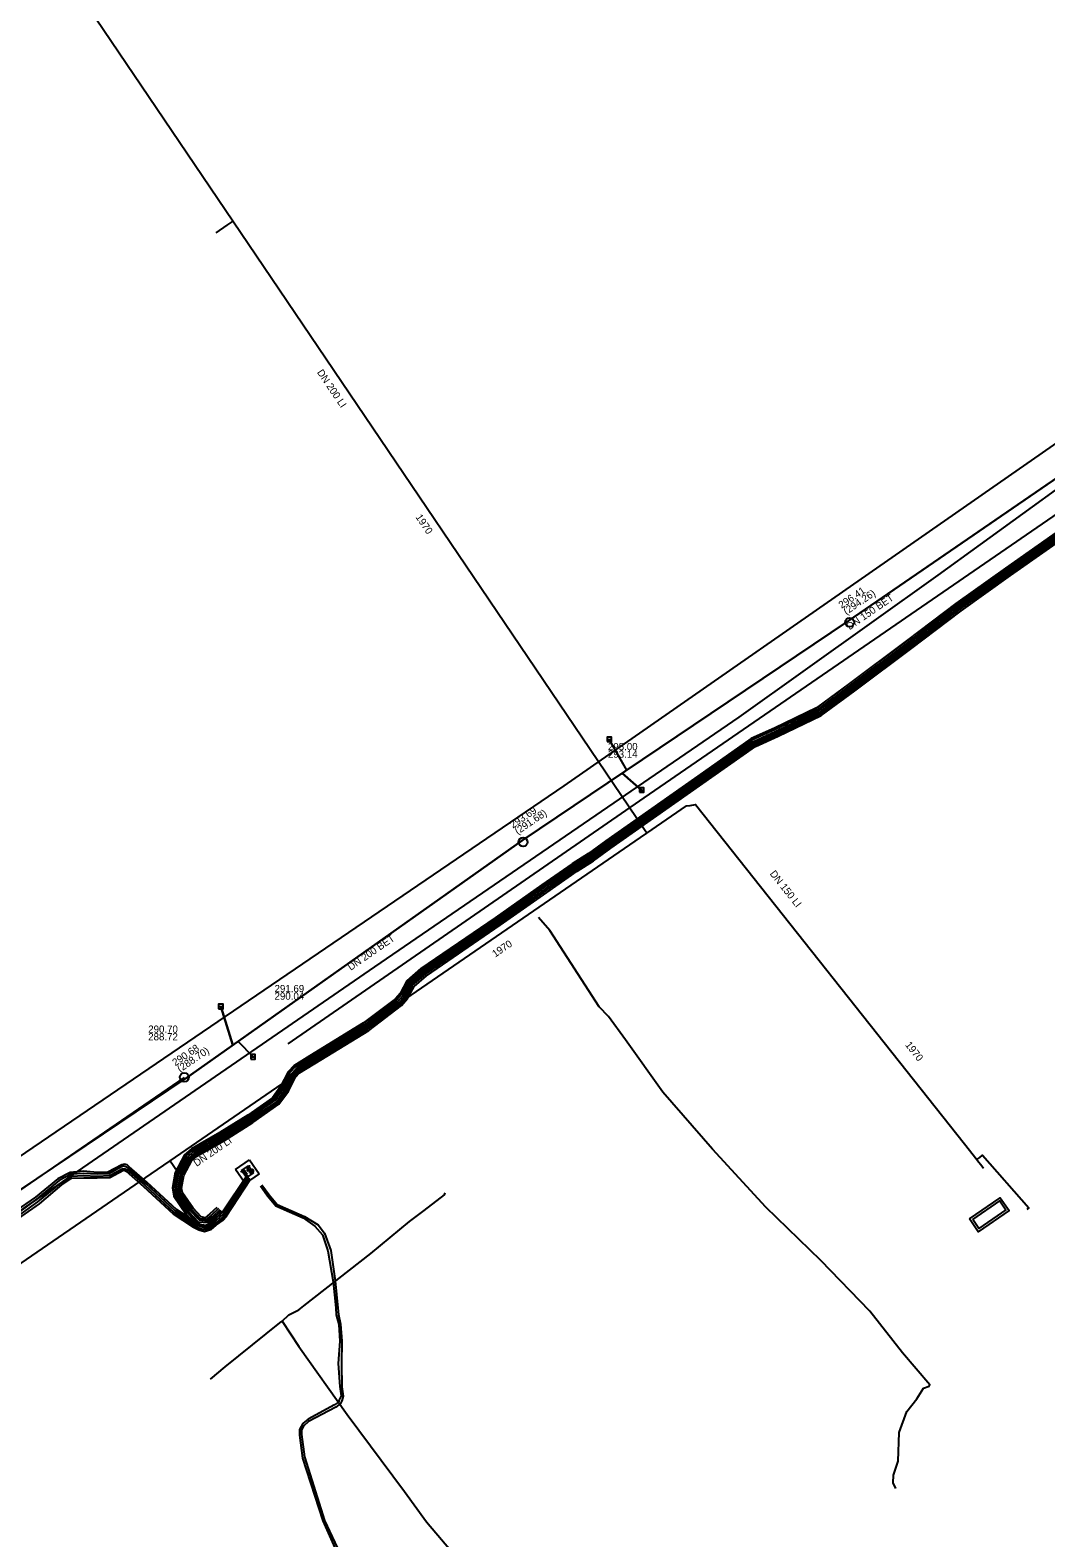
# Model space of a CAD drawing. Extents: x -600391 to -599491, y -1160176 to -1159402.
# Drawn here: x -599833.6 to -599721.4, y -1159847.4 to -1159680.9 of the extents above; entities that cross this region are included whole.
import ezdxf

# ---------------------------------------------------------------- set-up
doc = ezdxf.new("R2010")
doc.units = 0
for name, color, linetype in [('25', 7, 'Continuous'), ('CETIN_linie', 7, 'Continuous'), ('Vrstva 1', 7, 'Continuous'), ('Vrstva 13', 7, 'Continuous'), ('Vrstva 15', 7, 'Continuous'), ('Vrstva 19', 7, 'Continuous'), ('Vrstva 3', 7, 'Continuous'), ('Vrstva 4', 7, 'Continuous'), ('Vrstva 42', 7, 'Continuous'), ('Vrstva 43', 7, 'Continuous'), ('Vrstva 44', 7, 'Continuous'), ('Vrstva 45', 7, 'Continuous'), ('Vrstva 58', 7, 'Continuous')]:
    doc.layers.add(name, color=color, linetype=linetype)

# ---------------------------------------------------------------- blocks, each defined once
blk = doc.blocks.new('NN640')
at = {"layer": '25'}
for points in [[(-1.89, 1.89), (1.89, 1.89)], [(-1.89, -1.89), (-1.89, 1.89)], [(-1.26, 0.79), (-0.22, 0.79)], [(-0.73, 0.79), (-0.73, -0.79)], [(1.2, 0.66), (0.94, 0.79), (0.66, 0.79), (0.41, 0.66), (0.28, 0.47), (0.28, 0.41), (0.41, 0.22), (1.13, -0.16), (1.26, -0.32), (1.26, -0.47), (1.13, -0.66), (0.91, -0.79), (0.63, -0.79), (0.5, -0.73), (0.28, -0.6)], [(1.89, 1.89), (1.89, -1.89)], [(1.89, -1.89), (-1.89, -1.89)]]:
    blk.add_lwpolyline(points, dxfattribs=at)
blk = doc.blocks.new('VN640')
at = {"layer": '25'}
for points in [[(-1.89, 1.89), (1.89, 1.89)], [(-1.89, -1.89), (-1.89, 1.89)], [(-1.26, 0.79), (-0.22, 0.79)], [(-0.73, 0.79), (-0.73, -0.79)], [(1.2, 0.66), (0.94, 0.79), (0.66, 0.79), (0.41, 0.66), (0.28, 0.47), (0.28, 0.41), (0.41, 0.22), (1.13, -0.16), (1.26, -0.32), (1.26, -0.47), (1.13, -0.66), (0.91, -0.79), (0.63, -0.79), (0.5, -0.73), (0.28, -0.6)], [(1.89, 1.89), (1.89, -1.89)], [(1.89, -1.89), (-1.89, -1.89)]]:
    blk.add_lwpolyline(points, dxfattribs=at)

msp = doc.modelspace()

# ---------------------------------------------------------------- linework, layer by layer
at = {"layer": 'CETIN_linie'}
for points in [[(-599770.74, -1159788.79), (-599776.19, -1159780.37), (-599777.44, -1159778.92)], [(-599737.97, -1159842), (-599738.26, -1159841.36), (-599738.25, -1159840.51), (-599737.71, -1159838.96), (-599737.61, -1159835.8), (-599736.78, -1159833.5), (-599735.66, -1159832.09), (-599734.94, -1159830.92), (-599734.31, -1159830.68), (-599734.22, -1159830.53), (-599737.25, -1159826.99), (-599740.83, -1159822.4), (-599746.24, -1159816.81), (-599752.32, -1159810.93), (-599758.21, -1159804.53), (-599763.72, -1159798.22), (-599767.82, -1159792.44), (-599769.7, -1159789.87), (-599770.74, -1159788.79)]]:
    msp.add_lwpolyline(points, dxfattribs=at)
at = {"layer": 'Vrstva 1'}
for p, q in [((-599769.61, -1159759.26), (-599767.7, -1159762.67)), ((-599766.04, -1159764.86), (-599768.19, -1159763)), ((-599765.8, -1159765.71), (-599805.1, -1159792.9)), ((-599812.51, -1159788.77), (-599811.19, -1159793.03)), ((-599808.95, -1159794.32), (-599810.59, -1159792.61)), ((-599816.54, -1159796.61), (-599856.23, -1159823.78))]:
    msp.add_line(p, q, dxfattribs=at)
for points in [[(-599733.6, -1159557.62), (-599719.6, -1159585.05), (-599698.44, -1159625.81), (-599676.83, -1159671.44), (-599668.21, -1159694.85), (-599705.56, -1159720.34), (-599743.19, -1159746.17), (-599779.24, -1159770.44), (-599816.43, -1159796.74)], [(-599690.59, -1159713.98), (-599695.76, -1159717.54), (-599765.8, -1159765.71)], [(-599743.19, -1159746.17), (-599725.14, -1159733.78), (-599705.56, -1159720.34)], [(-599779.24, -1159770.44), (-599743.19, -1159746.17)], [(-599767.69, -1159762.67), (-599769.61, -1159759.26)], [(-599768.18, -1159763), (-599766.04, -1159764.86)], [(-599816.43, -1159796.74), (-599811.19, -1159793.03), (-599779.24, -1159770.44)], [(-599811.19, -1159793.04), (-599812.51, -1159788.77)], [(-599810.59, -1159792.61), (-599808.95, -1159794.32)], [(-599856.36, -1159823.61), (-599816.43, -1159796.74)]]:
    msp.add_lwpolyline(points, dxfattribs=at)
at = {"layer": 'Vrstva 13'}
for p, q in [((-599811.83, -1159702.47), (-599813.07, -1159703.31)), ((-599811.19, -1159702.04), (-599811.83, -1159702.47)), ((-599766.16, -1159770.09), (-599765.48, -1159769.63)), ((-599765.48, -1159769.63), (-599765.72, -1159769.27)), ((-599728.84, -1159805.9), (-599728.59, -1159806.22)), ((-599728.59, -1159806.22), (-599728.29, -1159806.6))]:
    msp.add_line(p, q, dxfattribs=at)
for points in [[(-599765.72, -1159769.27), (-599811.19, -1159702.04), (-599843.15, -1159654.78), (-599844.02, -1159653.49), (-599861.32, -1159627.71)], [(-599765.48, -1159769.63), (-599761.08, -1159766.6), (-599760.7, -1159766.55)], [(-599760.7, -1159766.55), (-599760.09, -1159766.47), (-599730.41, -1159803.93), (-599729.02, -1159805.67), (-599728.84, -1159805.9)], [(-599820.19, -1159807.23), (-599818.11, -1159805.79), (-599766.16, -1159770.09)], [(-599818.11, -1159805.79), (-599817.76, -1159806.3), (-599817.48, -1159806.71)], [(-599729.02, -1159805.67), (-599728.72, -1159805.43), (-599728.4, -1159805.18), (-599723.3, -1159810.98), (-599723.52, -1159811.16)], [(-599876.87, -1159846.48), (-599871.17, -1159842.26), (-599820.19, -1159807.23)], [(-599813.65, -1159829.92), (-599812.03, -1159828.56), (-599805.98, -1159823.71), (-599805.74, -1159823.5), (-599804.99, -1159822.8), (-599803.88, -1159822.26), (-599803.33, -1159821.8), (-599795.94, -1159816.03), (-599791.67, -1159812.5), (-599790.07, -1159811.29), (-599787.79, -1159809.54), (-599787.73, -1159809.35)], [(-599729.83, -1159812.2), (-599726.44, -1159809.88), (-599725.47, -1159811.27), (-599728.87, -1159813.63), (-599729.83, -1159812.2)], [(-599729.48, -1159812.27), (-599726.5, -1159810.23), (-599725.82, -1159811.21), (-599728.8, -1159813.28), (-599729.48, -1159812.27)], [(-599805.74, -1159823.5), (-599803.89, -1159826.29), (-599798.55, -1159833.83), (-599792.22, -1159842.31), (-599789.78, -1159845.65), (-599786.5, -1159849.58), (-599783.36, -1159853.59), (-599781.11, -1159856.56)]]:
    msp.add_lwpolyline(points, dxfattribs=at)
at = {"layer": 'Vrstva 19'}
msp.add_lwpolyline([(-599848.5, -1159814.71), (-599774.58, -1159764.38), (-599688.11, -1159704.16), (-599678.12, -1159696.61), (-599677.16, -1159697.83), (-599670.8, -1159706.19), (-599670.46, -1159707.2), (-599660.79, -1159721.25), (-599658.97, -1159723.88), (-599657.1, -1159725.77), (-599654.96, -1159728.17), (-599642.68, -1159733.56)], dxfattribs=at)
at = {"layer": 'Vrstva 3'}
for p, q in [((-599769.86, -1159759.26), (-599769.36, -1159759.26)), ((-599766.29, -1159764.86), (-599765.79, -1159764.86)), ((-599812.76, -1159788.77), (-599812.26, -1159788.77)), ((-599809.2, -1159794.32), (-599808.7, -1159794.32))]:
    msp.add_line(p, q, dxfattribs=at)
for points in [[(-599769.86, -1159759.51), (-599769.36, -1159759.51), (-599769.36, -1159759.01), (-599769.86, -1159759.01)], [(-599766.29, -1159765.11), (-599765.79, -1159765.11), (-599765.79, -1159764.61), (-599766.29, -1159764.61)], [(-599812.76, -1159789.02), (-599812.26, -1159789.02), (-599812.26, -1159788.52), (-599812.76, -1159788.52)], [(-599809.2, -1159794.57), (-599808.7, -1159794.57), (-599808.7, -1159794.07), (-599809.2, -1159794.07)]]:
    msp.add_lwpolyline(points, close=True, dxfattribs=at)
for centre in [(-599743.08, -1159746.34), (-599779.13, -1159770.61), (-599816.54, -1159796.57)]:
    msp.add_circle(centre, 0.5, dxfattribs=at)
at = {"layer": 'Vrstva 42'}
for points in [[(-599812.46, -1159811.34), (-599813.31, -1159812.13), (-599813.95, -1159812.64), (-599814.96, -1159812.56), (-599816.03, -1159811.42), (-599817.32, -1159809.55), (-599817.43, -1159808.81), (-599817.16, -1159807.23), (-599816.19, -1159805.39), (-599815.52, -1159804.78), (-599812.39, -1159803.02), (-599809.31, -1159801.08), (-599806.51, -1159799.12), (-599805.57, -1159797.79), (-599804.75, -1159796.22), (-599804.19, -1159795.63), (-599802.45, -1159794.55), (-599796.52, -1159790.9), (-599792.96, -1159788.2), (-599792.39, -1159787.55), (-599791.65, -1159786.16), (-599790.16, -1159784.88), (-599782, -1159779.29), (-599776.85, -1159775.66), (-599773.5, -1159773.33), (-599771.7, -1159772.18), (-599769.77, -1159770.8), (-599759.99, -1159763.9), (-599753.76, -1159759.52), (-599751.22, -1159758.37), (-599746.54, -1159756.12), (-599742.87, -1159753.42), (-599736.57, -1159748.71), (-599731.12, -1159744.58), (-599725.64, -1159740.68), (-599717.79, -1159735.15)], [(-599812.62, -1159811.21), (-599813.44, -1159811.98), (-599814.04, -1159812.47), (-599814.86, -1159812.37), (-599815.88, -1159811.29), (-599817.13, -1159809.48), (-599817.23, -1159808.81), (-599816.97, -1159807.3), (-599816.03, -1159805.52), (-599815.4, -1159804.95), (-599812.29, -1159803.19), (-599809.2, -1159801.25), (-599806.37, -1159799.27), (-599805.4, -1159797.9), (-599804.58, -1159796.33), (-599804.06, -1159795.78), (-599802.34, -1159794.73), (-599796.41, -1159791.07), (-599792.82, -1159788.35), (-599792.22, -1159787.66), (-599791.49, -1159786.29), (-599790.04, -1159785.04), (-599781.89, -1159779.46), (-599776.74, -1159775.83), (-599773.39, -1159773.5), (-599771.59, -1159772.35), (-599769.66, -1159770.96), (-599759.88, -1159764.07), (-599753.66, -1159759.69), (-599751.13, -1159758.55), (-599746.43, -1159756.29), (-599742.75, -1159753.58), (-599736.45, -1159748.87), (-599731, -1159744.74), (-599725.53, -1159740.85), (-599717.67, -1159735.31)], [(-599809.56, -1159807.36), (-599812.31, -1159811.47), (-599813.18, -1159812.28), (-599813.85, -1159812.82), (-599814.31, -1159812.98), (-599814.71, -1159812.86), (-599815.22, -1159812.6), (-599817.4, -1159811.19), (-599820.63, -1159808.2), (-599822.61, -1159806.47), (-599822.86, -1159806.23), (-599823.13, -1159806.16), (-599823.45, -1159806.24), (-599824.97, -1159807.04), (-599826.15, -1159807.09), (-599827.68, -1159806.95), (-599829.13, -1159807.08), (-599830.5, -1159807.79), (-599832.98, -1159809.8), (-599838.21, -1159813.43)], [(-599809.43, -1159807.52), (-599812.19, -1159811.64), (-599813.05, -1159812.43), (-599813.75, -1159813), (-599814.31, -1159813.19), (-599814.78, -1159813.05), (-599815.32, -1159812.77), (-599817.52, -1159811.35), (-599820.76, -1159808.35), (-599822.73, -1159806.63), (-599822.98, -1159806.45), (-599823.21, -1159806.38), (-599823.4, -1159806.44), (-599824.86, -1159807.23), (-599826.15, -1159807.29), (-599827.68, -1159807.21), (-599829.02, -1159807.28), (-599830.34, -1159807.97), (-599832.86, -1159810.03), (-599838.03, -1159813.63)], [(-599837.79, -1159813.96), (-599832.72, -1159810.33), (-599830.16, -1159808.28), (-599828.98, -1159807.49), (-599827.65, -1159807.41), (-599826.15, -1159807.49), (-599824.81, -1159807.43), (-599823.31, -1159806.65), (-599823.05, -1159806.67), (-599822.85, -1159806.79), (-599820.89, -1159808.5), (-599817.64, -1159811.51), (-599815.42, -1159812.94), (-599814.86, -1159813.24), (-599814.31, -1159813.4), (-599813.65, -1159813.18), (-599812.92, -1159812.58), (-599812.08, -1159811.8), (-599809.32, -1159807.69)], [(-599837.68, -1159814.13), (-599832.53, -1159810.55), (-599830.04, -1159808.44), (-599828.94, -1159807.73), (-599827.64, -1159807.67), (-599826.15, -1159807.69), (-599824.76, -1159807.63), (-599823.25, -1159806.84), (-599823.1, -1159806.87), (-599822.96, -1159806.95), (-599821.03, -1159808.65), (-599817.77, -1159811.67), (-599815.52, -1159813.12), (-599814.93, -1159813.42), (-599814.3, -1159813.61), (-599813.55, -1159813.36), (-599812.79, -1159812.73), (-599811.96, -1159811.97), (-599809.21, -1159807.84)], [(-599808.14, -1159808.55), (-599807.35, -1159809.68), (-599806.42, -1159810.78), (-599803.41, -1159812.11), (-599802.11, -1159813.02), (-599801.29, -1159813.97), (-599800.7, -1159815.73), (-599800.11, -1159819.16), (-599799.8, -1159822.04), (-599799.78, -1159822.81), (-599799.49, -1159823.87), (-599799.38, -1159825.72), (-599799.54, -1159828.19), (-599799.38, -1159830.74), (-599799.2, -1159831.77), (-599799.42, -1159832.2), (-599799.51, -1159832.46), (-599799.95, -1159832.75), (-599802.86, -1159834.34), (-599803.46, -1159834.8), (-599803.83, -1159835.48), (-599803.82, -1159836.1), (-599803.48, -1159838.62), (-599801.25, -1159845.57), (-599799.34, -1159849.85)], [(-599807.98, -1159808.45), (-599807.18, -1159809.56), (-599806.3, -1159810.62), (-599803.27, -1159811.94), (-599801.77, -1159812.88), (-599801.06, -1159813.8), (-599800.34, -1159815.69), (-599799.89, -1159819.04), (-599799.59, -1159822.09), (-599799.51, -1159822.76), (-599799.29, -1159823.83), (-599799.13, -1159825.71), (-599799.18, -1159828.22), (-599799.16, -1159830.76), (-599798.99, -1159831.78), (-599799.14, -1159832.32), (-599799.28, -1159832.61), (-599799.8, -1159833.02), (-599802.81, -1159834.6), (-599803.36, -1159835.09), (-599803.6, -1159835.56), (-599803.58, -1159836.04), (-599803.28, -1159838.48), (-599801.04, -1159845.52), (-599799.08, -1159849.75)]]:
    msp.add_lwpolyline(points, dxfattribs=at)
at = {"layer": 'Vrstva 44'}
for points in [[(-599812.34, -1159811.45), (-599812.71, -1159811.84), (-599813.62, -1159812.47), (-599814.81, -1159812.28), (-599815.8, -1159811.23), (-599817.03, -1159809.44), (-599817.13, -1159808.81), (-599816.87, -1159807.33), (-599815.95, -1159805.58), (-599815.34, -1159805.03), (-599812.24, -1159803.28), (-599809.14, -1159801.33), (-599806.3, -1159799.34), (-599805.31, -1159797.95), (-599804.5, -1159796.39), (-599804, -1159795.86), (-599802.29, -1159794.81), (-599796.35, -1159791.15), (-599792.75, -1159788.42), (-599792.14, -1159787.72), (-599791.41, -1159786.35), (-599789.98, -1159785.12), (-599781.83, -1159779.54), (-599776.68, -1159775.91), (-599773.33, -1159773.58), (-599771.53, -1159772.43), (-599769.6, -1159771.04), (-599759.82, -1159764.15), (-599753.61, -1159759.78), (-599751.09, -1159758.64), (-599746.38, -1159756.38), (-599742.69, -1159753.66), (-599736.39, -1159748.95), (-599730.94, -1159744.82), (-599725.47, -1159740.93), (-599717.61, -1159735.39)], [(-599812.77, -1159811.08), (-599813.57, -1159811.83), (-599814.14, -1159812.29), (-599814.76, -1159812.19), (-599815.72, -1159811.17), (-599816.93, -1159809.4), (-599817.03, -1159808.81), (-599816.77, -1159807.36), (-599815.87, -1159805.64), (-599815.28, -1159805.11), (-599812.19, -1159803.37), (-599809.09, -1159801.41), (-599806.23, -1159799.41), (-599805.22, -1159798), (-599804.42, -1159796.45), (-599803.94, -1159795.94), (-599802.24, -1159794.9), (-599796.29, -1159791.23), (-599792.68, -1159788.49), (-599792.06, -1159787.78), (-599791.33, -1159786.41), (-599789.92, -1159785.2), (-599781.77, -1159779.62), (-599776.62, -1159775.99), (-599773.28, -1159773.66), (-599771.47, -1159772.51), (-599769.54, -1159771.12), (-599759.76, -1159764.23), (-599753.56, -1159759.87), (-599751.05, -1159758.73), (-599746.33, -1159756.47), (-599742.63, -1159753.74), (-599736.33, -1159749.03), (-599730.88, -1159744.9), (-599725.41, -1159741.01), (-599717.55, -1159735.47)], [(-599812.93, -1159810.96), (-599813.71, -1159811.67), (-599814.24, -1159812.11), (-599814.66, -1159812), (-599815.57, -1159811.04), (-599816.74, -1159809.33), (-599816.83, -1159808.81), (-599816.58, -1159807.43), (-599815.71, -1159805.77), (-599815.16, -1159805.28), (-599812.09, -1159803.54), (-599808.97, -1159801.58), (-599806.09, -1159799.56), (-599805.05, -1159798.11), (-599804.25, -1159796.56), (-599803.81, -1159796.09), (-599802.13, -1159795.07), (-599796.18, -1159791.4), (-599792.54, -1159788.64), (-599791.89, -1159787.89), (-599791.17, -1159786.54), (-599789.8, -1159785.36), (-599781.66, -1159779.79), (-599776.51, -1159776.16), (-599773.16, -1159773.83), (-599771.36, -1159772.68), (-599769.43, -1159771.28), (-599759.65, -1159764.4), (-599753.46, -1159760.04), (-599750.96, -1159758.91), (-599746.22, -1159756.64), (-599742.51, -1159753.9), (-599736.21, -1159749.19), (-599730.76, -1159745.06), (-599725.3, -1159741.18), (-599717.43, -1159735.63)]]:
    msp.add_lwpolyline(points, dxfattribs=at)
at = {"layer": 'Vrstva 58'}
for points in [[(-599714.66, -1159727.57), (-599733.33, -1159741.14), (-599755.32, -1159756.8), (-599795.52, -1159784.39), (-599833.46, -1159810.48), (-599859.41, -1159829.59)], [(-599718.02, -1159734.82), (-599725.87, -1159740.36), (-599731.35, -1159744.26), (-599736.81, -1159748.39), (-599743.11, -1159753.1), (-599746.74, -1159755.78), (-599751.39, -1159758.01), (-599753.96, -1159759.17), (-599760.22, -1159763.58), (-599770.01, -1159770.47), (-599771.92, -1159771.85), (-599773.72, -1159773), (-599777.08, -1159775.34), (-599782.23, -1159778.96), (-599790.41, -1159784.56), (-599791.97, -1159785.91), (-599792.72, -1159787.32), (-599793.23, -1159787.91), (-599796.75, -1159790.57), (-599802.66, -1159794.21), (-599804.44, -1159795.31), (-599805.08, -1159795.98), (-599805.91, -1159797.58), (-599806.8, -1159798.84), (-599809.53, -1159800.75), (-599812.6, -1159802.68), (-599815.75, -1159804.46), (-599816.51, -1159805.14), (-599817.54, -1159807.1), (-599817.84, -1159808.8), (-599817.7, -1159809.71), (-599816.35, -1159811.67), (-599815.16, -1159812.93), (-599813.45, -1159813.21), (-599812.25, -1159812.37), (-599811.83, -1159811.93)], [(-599717.9, -1159734.99), (-599725.76, -1159740.52), (-599731.24, -1159744.42), (-599736.69, -1159748.55), (-599742.99, -1159753.26), (-599746.64, -1159755.95), (-599751.3, -1159758.19), (-599753.86, -1159759.34), (-599760.11, -1159763.74), (-599769.89, -1159770.63), (-599771.81, -1159772.02), (-599773.61, -1159773.16), (-599776.97, -1159775.5), (-599782.12, -1159779.13), (-599790.29, -1159784.72), (-599791.81, -1159786.03), (-599792.55, -1159787.43), (-599793.09, -1159788.05), (-599796.63, -1159790.74), (-599802.55, -1159794.38), (-599804.32, -1159795.47), (-599804.91, -1159796.1), (-599805.74, -1159797.69), (-599806.66, -1159798.98), (-599809.42, -1159800.91), (-599812.5, -1159802.85), (-599815.63, -1159804.62), (-599816.35, -1159805.27), (-599817.35, -1159807.17), (-599817.64, -1159808.81), (-599817.51, -1159809.63), (-599816.19, -1159811.54), (-599815.06, -1159812.75), (-599813.5, -1159813), (-599812.38, -1159812.22), (-599811.98, -1159811.79)]]:
    msp.add_lwpolyline(points, dxfattribs=at)

# ---------------------------------------------------------------- block references
at = {"layer": 'Vrstva 43', "xscale": 0.5000000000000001, "yscale": 0.5, "rotation": 35}
msp.add_blockref('NN640', (-599809.57, -1159807), dxfattribs=at)
at = {"layer": 'Vrstva 45', "xscale": 0.25000000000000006, "yscale": 0.25000000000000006, "rotation": 35}
msp.add_blockref('VN640', (-599809.57, -1159807), dxfattribs=at)

# ---------------------------------------------------------------- texts
at = {"layer": 'Vrstva 15'}
for s, rotation, p in [('DN 200 LI', 304.0687, (-599801.92, -1159718.74)), ('1970', 304.0687, (-599791.04, -1159734.72)), ('DN 150 LI', 308.3659, (-599751.94, -1159774.12)), ('1970', 34.4921, (-599782.21, -1159783.37)), ('1970', 308.3659, (-599736.99, -1159793.02)), ('DN 200 LI', 34.4921, (-599815.18, -1159806.48))]:
    msp.add_text(s, height=0.8, rotation=rotation, dxfattribs=at).set_placement(p)
at = {"layer": 'Vrstva 4'}
for s, rotation, p in [('296.41', 34.0134, (-599743.97, -1159744.85)), ('(294.26)', 34.0134, (-599743.44, -1159745.54)), ('DN 150 BET', 34.5176, (-599743.08, -1159747.22)), ('293.69', 34.0134, (-599780.26, -1159769.12)), ('(291.68)', 34.0134, (-599779.73, -1159769.81)), ('DN 200 BET', 34.685, (-599798.16, -1159784.83)), ('290.68', 34.0134, (-599817.53, -1159795.37)), ('(288.70)', 34.0134, (-599817, -1159796.06))]:
    msp.add_text(s, height=0.8, rotation=rotation, dxfattribs=at).set_placement(p)
for s, p in [('295.00', (-599769.76, -1159760.46)), ('293.14', (-599769.76, -1159761.29)), ('291.69', (-599806.57, -1159787.18)), ('290.04', (-599806.57, -1159788.01)), ('290.70', (-599820.52, -1159791.66)), ('288.72', (-599820.52, -1159792.5))]:
    msp.add_text(s, height=0.8, dxfattribs=at).set_placement(p)

doc.saveas('drawing.dxf')
